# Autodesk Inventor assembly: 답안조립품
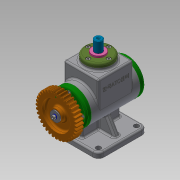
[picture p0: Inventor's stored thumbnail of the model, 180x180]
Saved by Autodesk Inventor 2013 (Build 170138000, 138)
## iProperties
Created: 2019-01
Part Number: 답안조립품
Document SubType Name: Assembly
Designer: Administrator
Author: Administrator
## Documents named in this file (18)
- C:\Users\Administrator\Desktop\390107V1019\답안조립품.iam
- C:\Users\Administrator\Desktop\390107V1019\본체.ipt
- C:\Users\Administrator\Desktop\390107V1019\뒤커버.ipt
- C:\Users\Administrator\Desktop\390107V1019\멈춤링.ipt
- C:\Users\Administrator\Desktop\390107V1019\베어링 6203.ipt
- C:\Users\Administrator\Desktop\390107V1019\볼트 M4.ipt
- C:\Users\Administrator\Desktop\390107V1019\부시.ipt
- C:\Users\Administrator\Desktop\390107V1019\상부커버.ipt
- C:\Users\Administrator\Desktop\390107V1019\스퍼기어.ipt
- C:\Users\Administrator\Desktop\390107V1019\스프링와셔.ipt
- C:\Users\Administrator\Desktop\390107V1019\스프링조립용 와셔.ipt
- C:\Users\Administrator\Desktop\390107V1019\슬라이더.ipt
- C:\Users\Administrator\Desktop\390107V1019\앞커버.ipt
- C:\Users\Administrator\Desktop\390107V1019\오일 실 17 30 5.ipt
- C:\Users\Administrator\Desktop\390107V1019\키 4x4x12.ipt
- C:\Users\Administrator\Desktop\390107V1019\편심축.ipt
- C:\Users\Administrator\Desktop\390107V1019\평와셔.ipt
- C:\Users\Administrator\Desktop\390107V1019\가변스프링1.ipt
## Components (1 placed, 1 different names)
1. 가변스프링1:1
